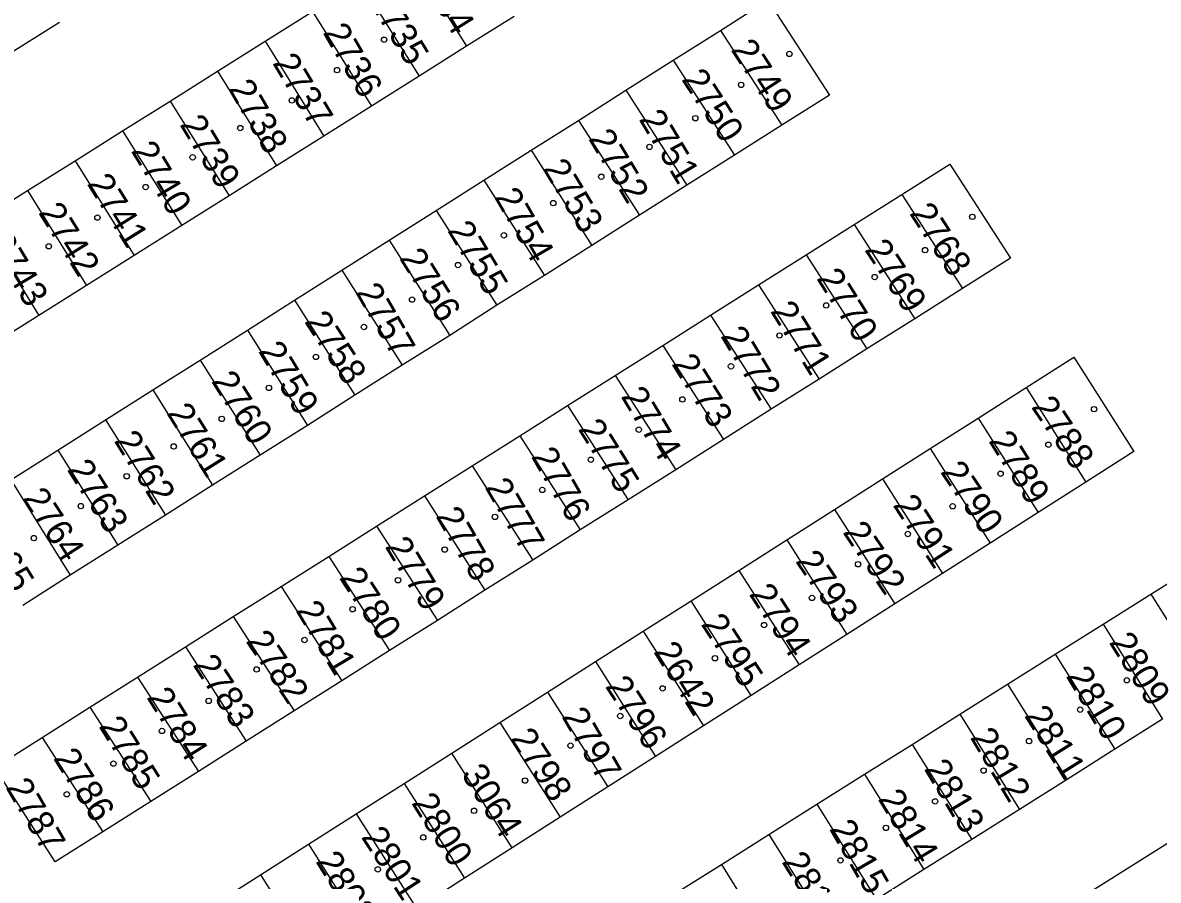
# Model space of a CAD drawing. Extents: x -679220 to -673243, y -1075091 to -1066557.
# Drawn here: x -676178 to -676104.3, y -1072438.2 to -1072382.5 of the extents above; entities that cross this region are included whole.
import ezdxf

# ---------------------------------------------------------------- set-up
doc = ezdxf.new("R2010")
doc.units = 0
for name, color, linetype in [('Hranice parcel', 7, 'Continuous'), ('Parcelní čísla', 7, 'Continuous'), ('Značky budov', 7, 'Continuous')]:
    doc.layers.add(name, color=color, linetype=linetype)

msp = doc.modelspace()

# ---------------------------------------------------------------- linework, layer by layer
at = {"layer": 'Hranice parcel'}
for p, q in [((-676153.05, -1072377.93), (-676149.21, -1072384.05)), ((-676156.13, -1072379.86), (-676152.3, -1072386)), ((-676162.3, -1072383.73), (-676159.21, -1072381.8)), ((-676159.21, -1072381.8), (-676155.39, -1072387.94)), ((-676146.12, -1072382.11), (-676149.21, -1072384.05)), ((-676175.65, -1072382.51), (-676178.71, -1072384.44)), ((-676135.8, -1072384.96), (-676132.73, -1072383.02)), ((-676132.73, -1072383.02), (-676128.74, -1072389.17)), ((-676165.38, -1072385.67), (-676162.3, -1072383.73)), ((-676162.3, -1072383.73), (-676158.47, -1072389.88)), ((-676149.21, -1072384.05), (-676152.3, -1072386)), ((-676138.88, -1072386.91), (-676135.8, -1072384.96)), ((-676135.8, -1072384.96), (-676131.82, -1072391.12)), ((-676168.46, -1072387.61), (-676165.38, -1072385.67)), ((-676165.38, -1072385.67), (-676161.55, -1072391.82)), ((-676152.3, -1072386), (-676155.39, -1072387.94)), ((-676141.95, -1072388.86), (-676138.88, -1072386.91)), ((-676138.88, -1072386.91), (-676134.91, -1072393.07)), ((-676171.55, -1072389.54), (-676168.46, -1072387.61)), ((-676168.46, -1072387.61), (-676164.63, -1072393.75)), ((-676155.39, -1072387.94), (-676158.47, -1072389.88)), ((-676174.63, -1072391.48), (-676171.55, -1072389.54)), ((-676171.55, -1072389.54), (-676167.71, -1072395.69)), ((-676145.03, -1072390.8), (-676141.95, -1072388.86)), ((-676141.95, -1072388.86), (-676137.99, -1072395.02)), ((-676128.74, -1072389.17), (-676131.82, -1072391.12)), ((-676158.47, -1072389.88), (-676161.55, -1072391.82)), ((-676148.1, -1072392.75), (-676145.03, -1072390.8)), ((-676145.03, -1072390.8), (-676141.08, -1072396.97)), ((-676177.71, -1072393.41), (-676174.63, -1072391.48)), ((-676174.63, -1072391.48), (-676170.8, -1072397.63)), ((-676131.82, -1072391.12), (-676134.91, -1072393.07)), ((-676161.55, -1072391.82), (-676164.63, -1072393.75)), ((-676151.18, -1072394.7), (-676148.1, -1072392.75)), ((-676148.1, -1072392.75), (-676144.16, -1072398.92)), ((-676134.91, -1072393.07), (-676137.99, -1072395.02)), ((-676180.79, -1072395.35), (-676177.71, -1072393.41)), ((-676177.71, -1072393.41), (-676173.89, -1072399.58)), ((-676164.63, -1072393.75), (-676167.71, -1072395.69)), ((-676124.06, -1072395.62), (-676120.95, -1072393.66)), ((-676120.95, -1072393.66), (-676117.01, -1072399.77)), ((-676154.24, -1072396.64), (-676151.18, -1072394.7)), ((-676151.18, -1072394.7), (-676147.24, -1072400.86)), ((-676180.79, -1072395.35), (-676176.98, -1072401.52)), ((-676137.99, -1072395.02), (-676141.08, -1072396.97)), ((-676167.71, -1072395.69), (-676170.8, -1072397.63)), ((-676127.16, -1072397.58), (-676124.06, -1072395.62)), ((-676124.06, -1072395.62), (-676120.12, -1072401.73)), ((-676157.31, -1072398.58), (-676154.24, -1072396.64)), ((-676154.24, -1072396.64), (-676150.31, -1072402.81)), ((-676170.8, -1072397.63), (-676173.89, -1072399.58)), ((-676141.08, -1072396.97), (-676144.16, -1072398.92)), ((-676130.26, -1072399.54), (-676127.16, -1072397.58)), ((-676127.16, -1072397.58), (-676123.22, -1072403.69)), ((-676160.38, -1072400.52), (-676157.31, -1072398.58)), ((-676157.31, -1072398.58), (-676153.39, -1072404.75)), ((-676144.16, -1072398.92), (-676147.24, -1072400.86)), ((-676173.89, -1072399.58), (-676176.98, -1072401.52)), ((-676133.37, -1072401.5), (-676130.26, -1072399.54)), ((-676130.26, -1072399.54), (-676126.32, -1072405.65)), ((-676117.01, -1072399.77), (-676120.12, -1072401.73)), ((-676163.44, -1072402.47), (-676160.38, -1072400.52)), ((-676160.38, -1072400.52), (-676156.47, -1072406.7)), ((-676147.24, -1072400.86), (-676150.31, -1072402.81)), ((-676176.98, -1072401.52), (-676180.07, -1072403.46)), ((-676136.47, -1072403.46), (-676133.37, -1072401.5)), ((-676133.37, -1072401.5), (-676129.43, -1072407.61)), ((-676120.12, -1072401.73), (-676123.22, -1072403.69)), ((-676166.51, -1072404.41), (-676163.44, -1072402.47)), ((-676163.44, -1072402.47), (-676159.54, -1072408.65)), ((-676150.31, -1072402.81), (-676153.39, -1072404.75)), ((-676139.57, -1072405.42), (-676136.47, -1072403.46)), ((-676136.47, -1072403.46), (-676132.53, -1072409.57)), ((-676123.22, -1072403.69), (-676126.32, -1072405.65)), ((-676169.59, -1072406.35), (-676166.51, -1072404.41)), ((-676166.51, -1072404.41), (-676162.62, -1072410.59)), ((-676153.39, -1072404.75), (-676156.47, -1072406.7)), ((-676142.67, -1072407.37), (-676139.57, -1072405.42)), ((-676139.57, -1072405.42), (-676135.63, -1072411.53)), ((-676126.32, -1072405.65), (-676129.43, -1072407.61)), ((-676172.66, -1072408.3), (-676169.59, -1072406.35)), ((-676169.59, -1072406.35), (-676165.7, -1072412.54)), ((-676116.01, -1072408.18), (-676112.89, -1072406.2)), ((-676112.89, -1072406.2), (-676109, -1072412.33)), ((-676156.47, -1072406.7), (-676159.54, -1072408.65)), ((-676145.76, -1072409.32), (-676142.67, -1072407.37)), ((-676142.67, -1072407.37), (-676138.73, -1072413.49)), ((-676129.43, -1072407.61), (-676132.53, -1072409.57)), ((-676175.74, -1072410.25), (-676172.66, -1072408.3)), ((-676172.66, -1072408.3), (-676168.77, -1072414.48)), ((-676159.54, -1072408.65), (-676162.62, -1072410.59)), ((-676119.11, -1072410.16), (-676116.01, -1072408.18)), ((-676116.01, -1072408.18), (-676112.11, -1072414.31)), ((-676148.86, -1072411.28), (-676145.76, -1072409.32)), ((-676145.76, -1072409.32), (-676141.83, -1072415.44)), ((-676132.53, -1072409.57), (-676135.63, -1072411.53)), ((-676122.22, -1072412.13), (-676119.11, -1072410.16)), ((-676119.11, -1072410.16), (-676115.21, -1072416.29)), ((-676178.81, -1072412.19), (-676175.74, -1072410.25)), ((-676175.74, -1072410.25), (-676171.86, -1072416.43)), ((-676162.62, -1072410.59), (-676165.7, -1072412.54)), ((-676151.95, -1072413.23), (-676148.86, -1072411.28)), ((-676148.86, -1072411.28), (-676144.92, -1072417.4)), ((-676135.63, -1072411.53), (-676138.73, -1072413.49)), ((-676178.81, -1072412.19), (-676174.94, -1072418.38)), ((-676125.32, -1072414.11), (-676122.22, -1072412.13)), ((-676122.22, -1072412.13), (-676118.31, -1072418.26)), ((-676109, -1072412.33), (-676112.11, -1072414.31)), ((-676165.7, -1072412.54), (-676168.77, -1072414.48)), ((-676155.06, -1072415.19), (-676151.95, -1072413.23)), ((-676151.95, -1072413.23), (-676148.02, -1072419.35)), ((-676138.73, -1072413.49), (-676141.83, -1072415.44)), ((-676168.77, -1072414.48), (-676171.86, -1072416.43)), ((-676128.43, -1072416.08), (-676125.32, -1072414.11)), ((-676125.32, -1072414.11), (-676121.42, -1072420.24)), ((-676112.11, -1072414.31), (-676115.21, -1072416.29)), ((-676158.15, -1072417.15), (-676155.06, -1072415.19)), ((-676155.06, -1072415.19), (-676151.11, -1072421.31)), ((-676141.83, -1072415.44), (-676144.92, -1072417.4)), ((-676131.53, -1072418.06), (-676128.43, -1072416.08)), ((-676128.43, -1072416.08), (-676124.52, -1072422.22)), ((-676171.86, -1072416.43), (-676174.94, -1072418.38)), ((-676115.21, -1072416.29), (-676118.31, -1072418.26)), ((-676161.26, -1072419.1), (-676158.15, -1072417.15)), ((-676158.15, -1072417.15), (-676154.21, -1072423.26)), ((-676144.92, -1072417.4), (-676148.02, -1072419.35)), ((-676134.64, -1072420.03), (-676131.53, -1072418.06)), ((-676131.53, -1072418.06), (-676127.62, -1072424.19)), ((-676118.31, -1072418.26), (-676121.42, -1072420.24)), ((-676104.78, -1072419.6), (-676101.68, -1072417.64)), ((-676174.94, -1072418.38), (-676178.03, -1072420.33)), ((-676164.36, -1072421.06), (-676161.26, -1072419.1)), ((-676161.26, -1072419.1), (-676157.31, -1072425.22)), ((-676148.02, -1072419.35), (-676151.11, -1072421.31)), ((-676107.89, -1072421.55), (-676104.78, -1072419.6)), ((-676104.78, -1072419.6), (-676100.92, -1072425.77)), ((-676137.74, -1072422.01), (-676134.64, -1072420.03)), ((-676130.73, -1072426.17), (-676134.64, -1072420.03)), ((-676121.42, -1072420.24), (-676124.52, -1072422.22)), ((-676167.46, -1072423.02), (-676164.36, -1072421.06)), ((-676164.36, -1072421.06), (-676160.41, -1072427.18)), ((-676151.11, -1072421.31), (-676154.21, -1072423.26)), ((-676110.99, -1072423.5), (-676107.89, -1072421.55)), ((-676107.89, -1072421.55), (-676104.03, -1072427.72)), ((-676140.85, -1072423.98), (-676137.74, -1072422.01)), ((-676137.74, -1072422.01), (-676133.83, -1072428.15)), ((-676124.52, -1072422.22), (-676127.62, -1072424.19)), ((-676170.57, -1072424.98), (-676167.46, -1072423.02)), ((-676167.46, -1072423.02), (-676163.52, -1072429.14)), ((-676154.21, -1072423.26), (-676157.31, -1072425.22)), ((-676143.95, -1072425.96), (-676140.85, -1072423.98)), ((-676140.85, -1072423.98), (-676136.94, -1072430.13)), ((-676127.62, -1072424.19), (-676130.73, -1072426.17)), ((-676114.09, -1072425.45), (-676110.99, -1072423.5)), ((-676110.99, -1072423.5), (-676107.13, -1072429.67)), ((-676173.67, -1072426.94), (-676170.57, -1072424.98)), ((-676170.57, -1072424.98), (-676166.62, -1072431.1)), ((-676157.31, -1072425.22), (-676160.41, -1072427.18)), ((-676117.18, -1072427.4), (-676114.09, -1072425.45)), ((-676114.09, -1072425.45), (-676110.22, -1072431.62)), ((-676147.06, -1072427.93), (-676143.95, -1072425.96)), ((-676143.95, -1072425.96), (-676140.04, -1072432.1)), ((-676130.73, -1072426.17), (-676133.83, -1072428.15)), ((-676176.77, -1072428.9), (-676173.67, -1072426.94)), ((-676173.67, -1072426.94), (-676169.72, -1072433.06)), ((-676160.41, -1072427.18), (-676163.52, -1072429.14)), ((-676120.28, -1072429.35), (-676117.18, -1072427.4)), ((-676117.18, -1072427.4), (-676113.32, -1072433.57)), ((-676104.03, -1072427.72), (-676107.13, -1072429.67)), ((-676150.16, -1072429.91), (-676147.06, -1072427.93)), ((-676147.06, -1072427.93), (-676143.14, -1072434.08)), ((-676133.83, -1072428.15), (-676136.94, -1072430.13)), ((-676176.77, -1072428.9), (-676172.83, -1072435.02)), ((-676163.52, -1072429.14), (-676166.62, -1072431.1)), ((-676123.38, -1072431.29), (-676120.28, -1072429.35)), ((-676120.28, -1072429.35), (-676116.42, -1072435.52)), ((-676153.27, -1072431.88), (-676150.16, -1072429.91)), ((-676146.25, -1072436.06), (-676150.16, -1072429.91)), ((-676107.13, -1072429.67), (-676110.22, -1072431.62)), ((-676136.94, -1072430.13), (-676140.04, -1072432.1)), ((-676166.62, -1072431.1), (-676169.72, -1072433.06)), ((-676126.48, -1072433.24), (-676123.38, -1072431.29)), ((-676123.38, -1072431.29), (-676119.52, -1072437.47)), ((-676156.38, -1072433.86), (-676153.27, -1072431.88)), ((-676153.27, -1072431.88), (-676149.35, -1072438.03)), ((-676140.04, -1072432.1), (-676143.14, -1072434.08)), ((-676110.22, -1072431.62), (-676113.32, -1072433.57)), ((-676169.72, -1072433.06), (-676172.83, -1072435.02)), ((-676129.58, -1072435.19), (-676126.48, -1072433.24)), ((-676126.48, -1072433.24), (-676122.61, -1072439.42)), ((-676113.32, -1072433.57), (-676116.42, -1072435.52)), ((-676159.48, -1072435.83), (-676156.38, -1072433.86)), ((-676156.38, -1072433.86), (-676152.45, -1072440.01)), ((-676143.14, -1072434.08), (-676146.25, -1072436.06)), ((-676132.67, -1072437.14), (-676129.58, -1072435.19)), ((-676129.58, -1072435.19), (-676125.71, -1072441.37)), ((-676162.59, -1072437.81), (-676159.48, -1072435.83)), ((-676159.48, -1072435.83), (-676155.56, -1072441.99)), ((-676116.42, -1072435.52), (-676119.52, -1072437.47)), ((-676146.25, -1072436.06), (-676149.35, -1072438.03)), ((-676135.77, -1072439.09), (-676132.67, -1072437.14)), ((-676132.67, -1072437.14), (-676128.81, -1072443.32)), ((-676165.69, -1072439.78), (-676162.59, -1072437.81)), ((-676162.59, -1072437.81), (-676158.66, -1072443.96)), ((-676149.35, -1072438.03), (-676152.45, -1072440.01)), ((-676119.52, -1072437.47), (-676122.61, -1072439.42))]:
    msp.add_line(p, q, dxfattribs=at)
for points in [[(-676132.73, -1072383.02), (-676129.65, -1072381.07), (-676125.66, -1072387.22), (-676128.74, -1072389.17)], [(-676120.95, -1072393.66), (-676117.85, -1072391.7), (-676113.91, -1072397.81), (-676117.01, -1072399.77)], [(-676112.89, -1072406.2), (-676109.78, -1072404.22), (-676105.89, -1072410.35), (-676109, -1072412.33)], [(-676156.45, -1072486.01), (-676164.15, -1072473.75), (-676076.31, -1072418.55), (-676074.81, -1072421.15)], [(-676172.83, -1072435.02), (-676175.93, -1072436.98), (-676179.86, -1072430.85), (-676176.77, -1072428.9)]]:
    msp.add_lwpolyline(points, dxfattribs=at)
at = {"layer": 'Značky budov'}
for centre in [(-676154.567, -1072383.629), (-676128.257, -1072384.549), (-676157.617, -1072385.599), (-676131.387, -1072386.559), (-676160.557, -1072387.569), (-676134.357, -1072388.719), (-676163.907, -1072389.359), (-676137.337, -1072390.579), (-676166.997, -1072391.259), (-676140.467, -1072392.519), (-676170.047, -1072393.189), (-676143.587, -1072394.229), (-676173.177, -1072395.169), (-676116.377, -1072395.119), (-676146.787, -1072396.319), (-676176.337, -1072397.029), (-676119.447, -1072397.279), (-676149.767, -1072398.249), (-676122.717, -1072399.029), (-676152.747, -1072400.489), (-676125.867, -1072400.869), (-676155.877, -1072402.269), (-676128.897, -1072402.819), (-676158.997, -1072404.209), (-676132.047, -1072404.819), (-676162.047, -1072406.219), (-676135.197, -1072406.969), (-676108.477, -1072407.599), (-676165.107, -1072408.229), (-676138.037, -1072408.929), (-676168.227, -1072410.019), (-676111.437, -1072409.909), (-676141.147, -1072410.879), (-676114.547, -1072411.789), (-676171.277, -1072411.949), (-676144.297, -1072412.839), (-676174.257, -1072413.889), (-676117.657, -1072413.899), (-676147.367, -1072414.589), (-676177.307, -1072415.969), (-676120.567, -1072415.699), (-676150.637, -1072416.709), (-676123.797, -1072417.659), (-676153.667, -1072418.699), (-676126.787, -1072419.849), (-676156.617, -1072420.579), (-676129.897, -1072421.609), (-676159.737, -1072422.579), (-676133.087, -1072423.759), (-676162.847, -1072424.489), (-676136.487, -1072425.719), (-676106.347, -1072425.189), (-676165.957, -1072426.529), (-676109.377, -1072427.099), (-676139.237, -1072427.509), (-676168.987, -1072428.479), (-676142.467, -1072429.429), (-676112.697, -1072429.139), (-676172.137, -1072430.599), (-676145.417, -1072431.699), (-676115.647, -1072431.049), (-676175.167, -1072432.589), (-676118.797, -1072433.049), (-676148.727, -1072433.659), (-676152.027, -1072435.389), (-676121.987, -1072434.769), (-676124.937, -1072436.879), (-676154.977, -1072437.459)]:
    msp.add_circle(centre, 0.175, dxfattribs=at)

# ---------------------------------------------------------------- texts
at = {"layer": 'Parcelní čísla'}
for s, rotation, p in [('2734', 302, (-676152.71, -1072379.16)), ('2735', 301, (-676155.628, -1072381.087)), ('2736', 300, (-676158.576, -1072383.155)), ('2749', 303, (-676132.092, -1072384.272)), ('2737', 301, (-676161.848, -1072385.137)), ('2750', 303, (-676135.292, -1072386.202)), ('2738', 300, (-676164.716, -1072386.804)), ('2739', 301, (-676167.868, -1072389.127)), ('2751', 301, (-676138.058, -1072388.787)), ('2752', 301, (-676141.338, -1072390.047)), ('2740', 301, (-676171.028, -1072390.837)), ('2753', 301, (-676144.308, -1072391.987)), ('2741', 302, (-676173.89, -1072392.97)), ('2754', 300, (-676147.446, -1072393.834)), ('2742', 302, (-676177.05, -1072394.84)), ('2768', 303, (-676120.502, -1072394.892)), ('2755', 301, (-676150.488, -1072396.007)), ('2743', 301, (-676180.338, -1072396.757)), ('2769', 303, (-676123.412, -1072397.252)), ('2756', 302, (-676153.61, -1072397.81)), ('2770', 302, (-676126.53, -1072399.11)), ('2757', 300, (-676156.456, -1072400.015)), ('2771', 302, (-676129.53, -1072401.24)), ('2758', 303, (-676159.782, -1072401.912)), ('2772', 301, (-676132.758, -1072402.847)), ('2759', 301, (-676162.768, -1072403.827)), ('2773', 302, (-676135.94, -1072404.66)), ('2760', 302, (-676165.82, -1072405.78)), ('2774', 301, (-676139.228, -1072406.767)), ('2761', 302, (-676168.72, -1072407.86)), ('2788', 304, (-676112.594, -1072407.455)), ('2775', 302, (-676142.01, -1072408.89)), ('2762', 302, (-676172.14, -1072409.65)), ('2789', 302, (-676115.36, -1072409.66)), ('2776', 300, (-676145.056, -1072410.665)), ('2763', 302, (-676175.19, -1072411.51)), ('2790', 304, (-676118.494, -1072411.675)), ('2777', 300, (-676148.056, -1072412.665)), ('2764', 303, (-676178.092, -1072413.382)), ('2791', 303, (-676121.572, -1072413.822)), ('2778', 300, (-676151.246, -1072414.535)), ('2765', 302, (-676181.3, -1072415.31)), ('2792', 304, (-676124.834, -1072415.585)), ('2779', 301, (-676154.548, -1072416.507)), ('2793', 304, (-676127.904, -1072417.465)), ('2780', 303, (-676157.522, -1072418.532)), ('2794', 303, (-676130.912, -1072419.602)), ('2781', 301, (-676160.338, -1072420.657)), ('2795', 303, (-676134.032, -1072421.552)), ('2782', 304, (-676163.584, -1072422.655)), ('2642', 302, (-676137.11, -1072423.34)), ('2809', 302, (-676107.54, -1072422.73)), ('2783', 303, (-676167.022, -1072424.192)), ('2796', 303, (-676140.252, -1072425.582)), ('2810', 301, (-676110.338, -1072424.907)), ('2784', 302, (-676170.02, -1072426.3)), ('2797', 300, (-676143.066, -1072427.545)), ('2811', 302, (-676113.04, -1072427.48)), ('2785', 302, (-676173.13, -1072428.17)), ('2798', 303, (-676146.432, -1072428.972)), ('2812', 301, (-676116.558, -1072428.897)), ('2786', 302, (-676176.08, -1072430.25)), ('3064', 302, (-676149.6, -1072431.28)), ('2813', 301, (-676119.548, -1072430.937)), ('2787', 300, (-676179.166, -1072432.135)), ('2814', 301, (-676122.538, -1072432.887)), ('2800', 302, (-676152.83, -1072433.15)), ('2815', 300, (-676125.696, -1072434.834)), ('2801', 303, (-676156.092, -1072435.362)), ('2802', 302, (-676159.05, -1072436.94)), ('2816', 302, (-676128.79, -1072436.97))]:
    msp.add_text(s, height=1.7, rotation=rotation, dxfattribs=at).set_placement(p)

doc.saveas('drawing.dxf')
